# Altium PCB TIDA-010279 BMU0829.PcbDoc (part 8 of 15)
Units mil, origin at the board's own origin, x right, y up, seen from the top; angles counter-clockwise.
Board outline 11269.69 x 4438.98 mil, 4 copper layers (Top Layer, Signal Layer 1, Signal Layer 2, Bottom Layer), stack 61.6 mil thick; 1494 components, 725 nets, 3766 pads, 2728 vias.
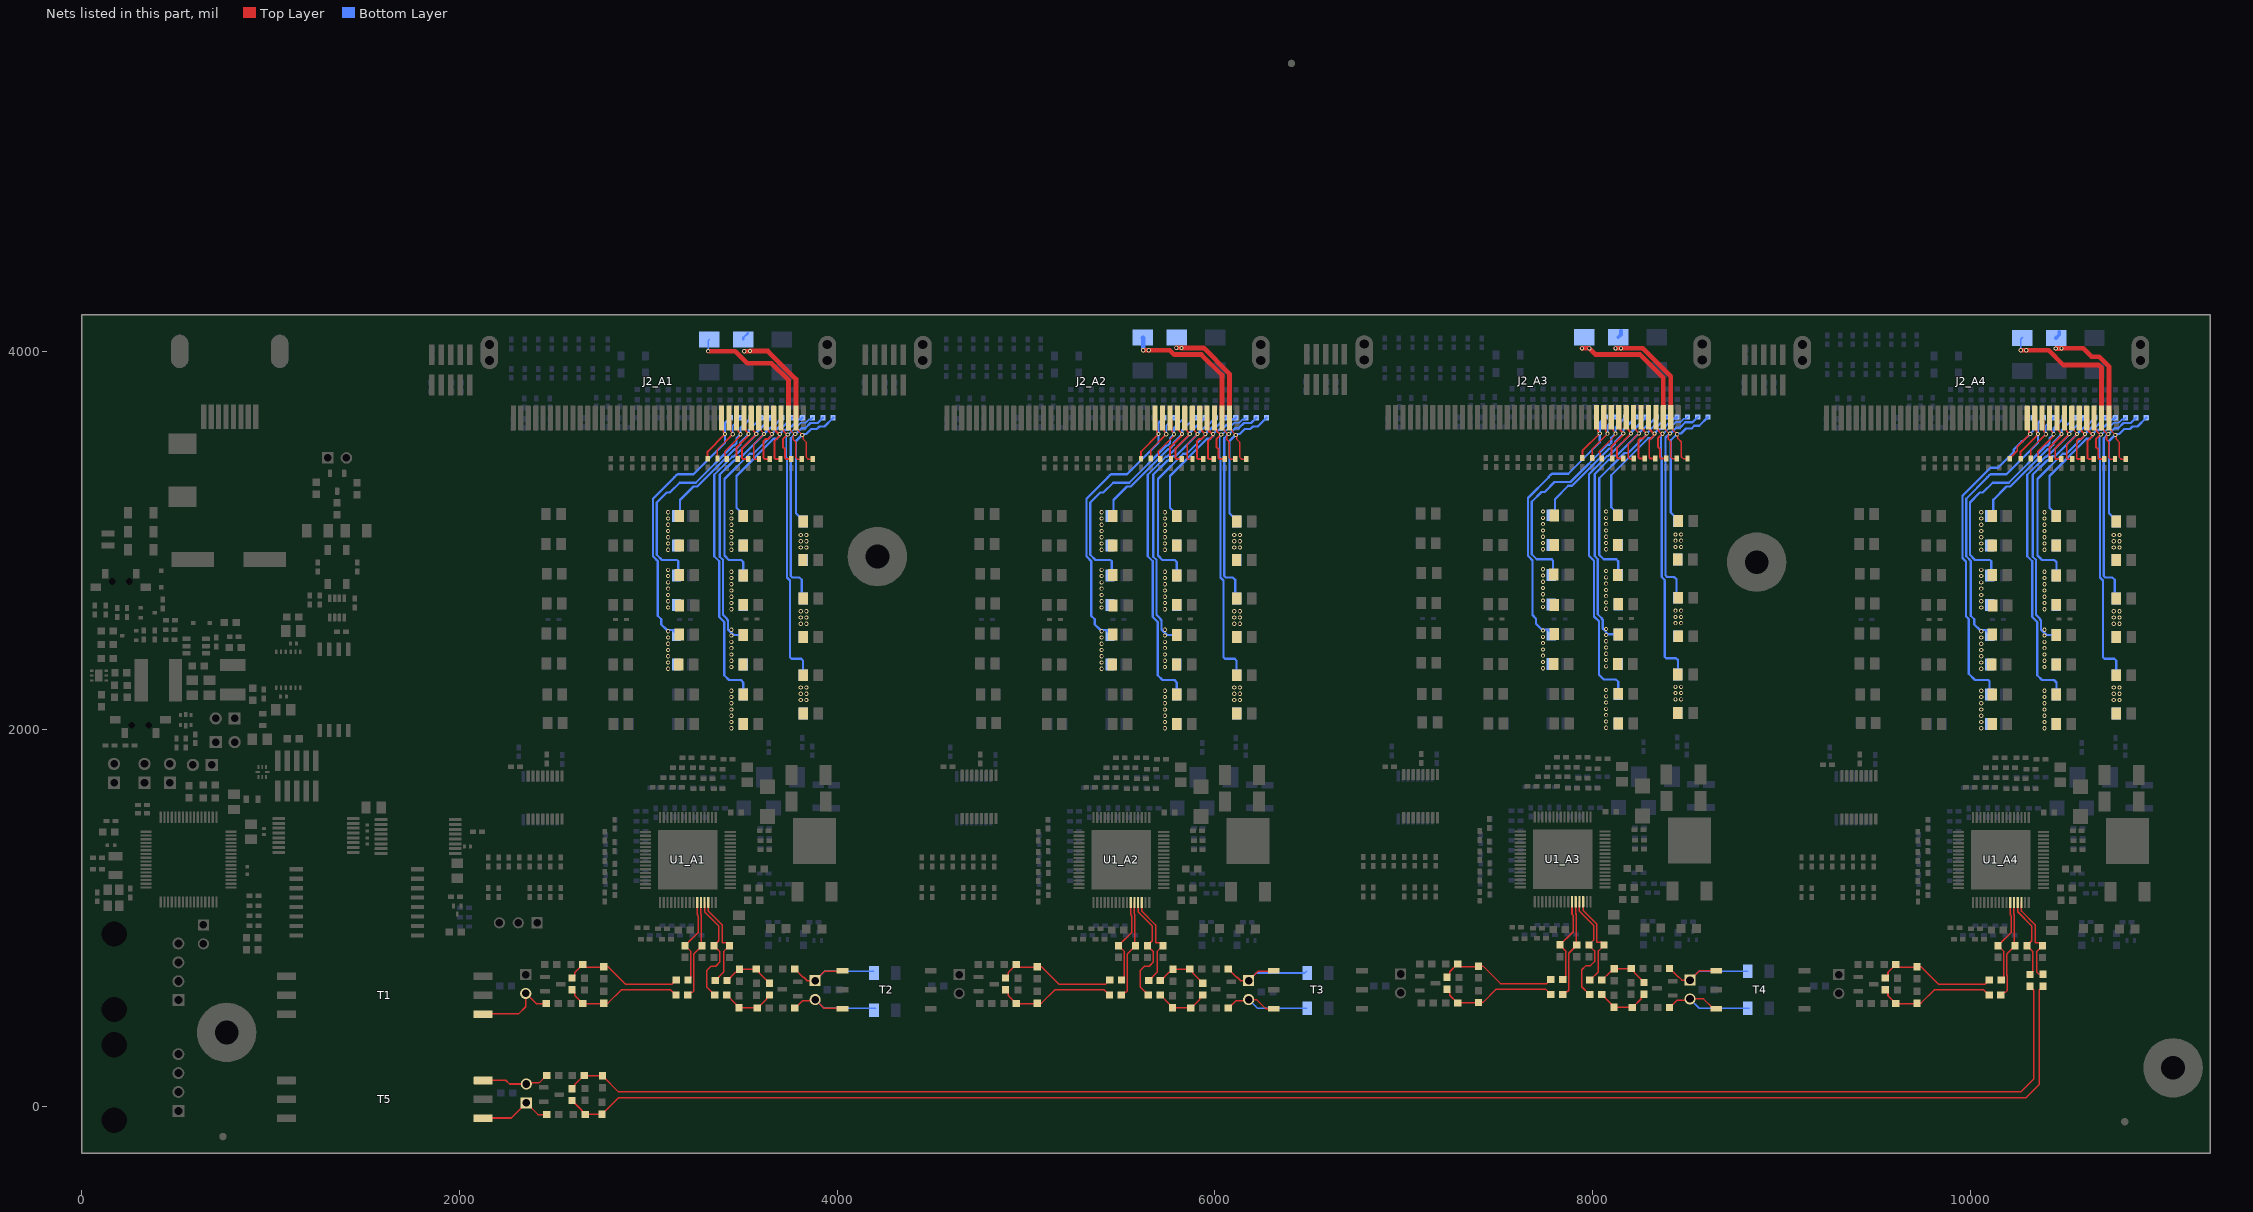
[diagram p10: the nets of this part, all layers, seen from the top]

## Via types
v1: diameter 22.01, hole 12.01, Top Layer to Bottom Layer, tented both sides, 2578 vias
v2: diameter 19.68, hole 7.87, Top Layer to Bottom Layer, tented both sides, 144 vias
v3: diameter 92.52, hole 49.21, Top Layer to Bottom Layer, 4 vias
v4: diameter 19.68, hole 7.87, Top Layer to Bottom Layer, 2 vias

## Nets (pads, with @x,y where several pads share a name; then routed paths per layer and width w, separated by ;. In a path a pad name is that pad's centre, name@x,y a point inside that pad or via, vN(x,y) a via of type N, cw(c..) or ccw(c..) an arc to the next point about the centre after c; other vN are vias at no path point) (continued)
CELL8_A4: C50_A4.1 J2_A4.14 R56_A4.1 R59_A4.1 R63_A4.1 R67_A4.1 R100_A4.1 | length 2015.9
  Top Layer w10: R100_A4.1@10208.36,3431.26 10208.36,3435.19 10247.35,3474.19 10247.35,3494.93 10314.24,3561.81 v1(10316.31,3561.81) 10316.31,3565.06 10309.15,3572.22 10309.15,3638.34 J2_A4.14@10300.37,3647.12
  Bottom Layer w10: 10271.84,3523.52 10278.02,3523.52 v1(10316.31,3561.81) 10316.31,3565.06 10331.52,3580.28 C50_A4.1@10331.52,3648.58
  Bottom Layer w12: R67_A4.1@10100.95,2183.48 10100.95,2252.87 10093.92,2259.9 10024.33,2259.9 9991.15,2293.08 9991.15,2582.34 9976.37,2597.12 9976.37,2886.04 9971.64,2890.76 9971.64,2891.9 9957.23,2906.31 9957.23,3235.23 10106.01,3384.01 10146,3384.01 10228.58,3466.59 10228.58,3480.26 10271.84,3523.52
  other v1: 10056.74,2004.25 10056.74,2037.44 10056.74,2070.62 10056.74,2103.81 10056.74,2136.99 10056.74,2170.17 10056.74,2203.36
CELL9_A1: C47_A1.1 J2_A1.35 R43_A1.1 R46_A1.1 R49_A1.1 R53_A1.1 R90_A1.1 | length 1701.8
  Top Layer w10: R90_A1.1@3313.38,3431.26 3313.38,3469.37 v1(3405.83,3561.81) 3405.83,3565.06 3396.68,3574.21 3396.68,3638.34 J2_A1.35@3387.9,3647.12
  Bottom Layer w12: R46_A1.1@3149.11,2498.57 3149.11,2505.07 3130.11,2524.07 3098.4,2524.07 3068.22,2554.26 3068.22,2581.54 3049.26,2600.5 3049.26,2889.41 3041.06,2897.6 3041.06,2898.74 3025.26,2914.54 3025.26,3219.97 3135.7,3330.41 3135.7,3332.52 3147.34,3344.16 3149.45,3344.16 3154.09,3348.8 3238.9,3348.8 3405.83,3515.73 v1(3405.83,3561.81) 3405.83,3620.11 C47_A1.1@3434.3,3648.58
  other v1: 3104.9,2319.21 3104.9,2352.4 3104.9,2385.58 3104.9,2418.77 3104.9,2451.95 3104.9,2485.14 3104.9,2518.32
CELL9_A2: C47_A2.1 J2_A2.35 R43_A2.1 R46_A2.1 R49_A2.1 R53_A2.1 R90_A2.1 | length 1701.8
  Top Layer w10: R90_A2.1@5608.4,3431.26 5608.4,3469.37 v1(5700.85,3561.81) 5700.85,3565.06 5691.7,3574.21 5691.7,3638.34 J2_A2.35@5682.92,3647.12
  Bottom Layer w12: R46_A2.1@5444.12,2498.57 5444.12,2505.07 5425.12,2524.07 5393.42,2524.07 5363.23,2554.26 5363.23,2581.54 5344.27,2600.5 5344.27,2889.41 5336.08,2897.6 5336.08,2898.74 5320.27,2914.54 5320.27,3219.97 5430.71,3330.41 5430.71,3332.52 5442.35,3344.16 5444.47,3344.16 5449.1,3348.8 5533.92,3348.8 5700.85,3515.73 v1(5700.85,3561.81) 5700.85,3620.11 C47_A2.1@5729.31,3648.58
  other v1: 5399.92,2319.21 5399.92,2352.4 5399.92,2385.58 5399.92,2418.77 5399.92,2451.95 5399.92,2485.14 5399.92,2518.32
CELL9_A3: C47_A3.1 J2_A3.35 R43_A3.1 R46_A3.1 R49_A3.1 R53_A3.1 R90_A3.1 | length 1701.8
  Top Layer w10: R90_A3.1@7945,3434.46 7945,3472.57 v1(8037.44,3565.02) 8037.44,3568.27 8028.29,3577.42 8028.29,3641.55 J2_A3.35@8019.51,3650.33
  Bottom Layer w12: R46_A3.1@7780.72,2501.78 7780.72,2508.28 7761.72,2527.28 7730.02,2527.28 7699.83,2557.47 7699.83,2584.74 7680.87,2603.7 7680.87,2892.62 7672.68,2900.81 7672.68,2901.94 7656.87,2917.75 7656.87,3223.18 7767.31,3333.62 7767.31,3335.73 7778.95,3347.37 7781.06,3347.37 7785.7,3352.01 7870.51,3352.01 8037.44,3518.94 v1(8037.44,3565.02) 8037.44,3623.32 C47_A3.1@8065.91,3651.79
  other v1: 7736.51,2322.42 7736.51,2355.6 7736.51,2388.79 7736.51,2421.97 7736.51,2455.16 7736.51,2488.34 7736.51,2521.53
CELL9_A4: C47_A4.1 J2_A4.35 R43_A4.1 R46_A4.1 R49_A4.1 R53_A4.1 R90_A4.1 | length 1701.8
  Top Layer w10: R90_A4.1@10265.23,3431.26 10265.23,3469.37 v1(10357.67,3561.81) 10357.67,3565.06 10348.52,3574.21 10348.52,3638.34 J2_A4.35@10339.74,3647.12
  Bottom Layer w12: R46_A4.1@10100.95,2498.57 10100.95,2505.07 10081.95,2524.07 10050.25,2524.07 10020.06,2554.26 10020.06,2581.54 10001.1,2600.5 10001.1,2889.41 9992.91,2897.61 9992.91,2898.74 9977.1,2914.54 9977.1,3219.97 10087.54,3330.41 10087.54,3332.52 10099.18,3344.16 10101.29,3344.16 10105.93,3348.8 10190.74,3348.8 10357.67,3515.73 v1(10357.67,3561.81) 10357.67,3620.11 C47_A4.1@10386.14,3648.58
  other v1: 10056.74,2319.21 10056.74,2352.4 10056.74,2385.58 10056.74,2418.77 10056.74,2451.95 10056.74,2485.14 10056.74,2518.32
CELL10_A1: C42_A1.1 J2_A1.36 R28_A1.1 R31_A1.1 R34_A1.1 R39_A1.1 R83_A1.1 | length 1467.6
  Top Layer w8: R83_A1.1@3415.33,3429.13 3408.04,3436.42 3408.04,3456.88 3404.04,3460.88 3404.04,3468.98 3485.87,3550.82 3485.87,3558.37 v1(3488.55,3561.05) 3488.55,3564.84 3476.42,3576.98 3476.42,3637.34 J2_A1.36@3466.64,3647.12
  Bottom Layer w12: R31_A1.1@3149.11,2813.66 3157.85,2822.41 3157.85,2888.35 3150.82,2895.38 3072.53,2895.38 3045.13,2922.78 3045.13,3200.09 3097.29,3252.25 3113.76,3252.25 3165.92,3304.41 3250.73,3304.41 3448.14,3501.83 3455.42,3501.83 3467.07,3513.47 3467.07,3539.56 v1(3488.55,3561.05) 3488.55,3594.16 C42_A1.1@3542.97,3648.58
  other v1: 3104.9,2644.02 3104.9,2677.2 3104.9,2710.38 3104.9,2743.57 3104.9,2776.75 3104.9,2809.94 3104.9,2843.12
CELL10_A2: C42_A2.1 J2_A2.36 R28_A2.1 R31_A2.1 R34_A2.1 R39_A2.1 R83_A2.1 | length 1467.6
  Top Layer w8: R83_A2.1@5710.34,3429.13 5703.05,3436.42 5703.05,3456.88 5699.05,3460.88 5699.05,3468.98 5780.89,3550.82 5780.89,3558.37 v1(5783.57,3561.05) 5783.57,3564.84 5771.44,3576.98 5771.44,3637.34 J2_A2.36@5761.66,3647.12
  Bottom Layer w12: R31_A2.1@5444.12,2813.66 5452.87,2822.41 5452.87,2888.35 5445.84,2895.38 5367.55,2895.38 5340.15,2922.78 5340.15,3200.09 5392.31,3252.25 5408.77,3252.25 5460.93,3304.41 5545.74,3304.41 5743.16,3501.83 5750.44,3501.83 5762.08,3513.47 5762.08,3539.56 v1(5783.57,3561.05) 5783.57,3594.16 C42_A2.1@5837.99,3648.58
  other v1: 5399.92,2644.02 5399.92,2677.2 5399.92,2710.38 5399.92,2743.57 5399.92,2776.75 5399.92,2809.94 5399.92,2843.12
CELL10_A3: C42_A3.1 J2_A3.36 R28_A3.1 R31_A3.1 R34_A3.1 R39_A3.1 R83_A3.1 | length 1467.6
  Top Layer w8: R83_A3.1@8046.94,3432.34 8039.65,3439.63 8039.65,3460.09 8035.65,3464.09 8035.65,3472.19 8117.49,3554.02 8117.49,3561.58 v1(8120.17,3564.26) 8120.17,3568.05 8108.03,3580.18 8108.03,3640.55 J2_A3.36@8098.25,3650.33
  Bottom Layer w12: R31_A3.1@7780.72,2816.87 7789.47,2825.62 7789.47,2891.55 7782.44,2898.58 7704.15,2898.58 7676.74,2925.98 7676.74,3203.3 7728.9,3255.46 7745.37,3255.46 7797.53,3307.62 7882.34,3307.62 8079.76,3505.04 8087.04,3505.04 8098.68,3516.68 8098.68,3542.77 v1(8120.17,3564.26) 8120.17,3597.37 C42_A3.1@8174.58,3651.79
  other v1: 7736.51,2647.22 7736.51,2680.41 7736.51,2713.59 7736.51,2746.78 7736.51,2779.96 7736.51,2813.15 7736.51,2846.33
CELL10_A4: C42_A4.1 J2_A4.36 R28_A4.1 R31_A4.1 R34_A4.1 R39_A4.1 R83_A4.1 | length 1467.6
  Top Layer w8: R83_A4.1@10367.17,3429.13 10359.88,3436.42 10359.88,3456.88 10355.88,3460.88 10355.88,3468.98 10437.72,3550.82 10437.72,3558.37 v1(10440.4,3561.05) 10440.4,3564.84 10428.26,3576.98 10428.26,3637.34 J2_A4.36@10418.48,3647.12
  Bottom Layer w12: R31_A4.1@10100.95,2813.66 10109.7,2822.41 10109.7,2888.35 10102.67,2895.38 10024.37,2895.38 9996.97,2922.78 9996.97,3200.09 10049.13,3252.25 10065.6,3252.25 10117.76,3304.41 10202.57,3304.41 10399.99,3501.83 10407.27,3501.83 10418.91,3513.47 10418.91,3539.56 v1(10440.4,3561.05) 10440.4,3594.16 C42_A4.1@10494.81,3648.58
  other v1: 10056.74,2644.02 10056.74,2677.2 10056.74,2710.38 10056.74,2743.57 10056.74,2776.75 10056.74,2809.94 10056.74,2843.12
CELL11_A1: C39_A1.1 J2_A1.16 R14_A1.1 R17_A1.1 R21_A1.1 R24_A1.1 R75_A1.1 | length 975
  Top Layer w10: R75_A1.1@3472.2,3429.13 3467.38,3433.95 3467.38,3492.52 v1@3533.3,3558.43 ; J2_A1.16@3506.01,3647.12 3514.79,3638.34 3514.79,3580.19 3529.92,3565.06 v1(3529.92,3561.81)
  Bottom Layer w12: R24_A1.1@3149.11,3128.75 3168.11,3147.75 3168.11,3213.54 3239.11,3284.54 3258.96,3284.54 3456.38,3481.96 3463.66,3481.96 3486.94,3505.24 3486.94,3517.94 v1@3530.36,3561.37 ; v1(3529.92,3561.81) 3531.83,3563.73 3531.83,3583.01 C39_A1.1@3597.4,3648.58
  other v1: 3104.9,2949.13 3104.9,2982.32 3104.9,3015.5 3104.9,3048.69 3104.9,3081.87 3104.9,3115.06 3104.9,3148.24
CELL11_A2: C39_A2.1 J2_A2.16 R14_A2.1 R17_A2.1 R21_A2.1 R24_A2.1 R75_A2.1 | length 975
  Top Layer w10: R75_A2.1@5767.21,3429.13 5762.39,3433.95 5762.39,3492.52 v1@5828.31,3558.43 ; J2_A2.16@5801.03,3647.12 5809.81,3638.34 5809.81,3580.19 5824.93,3565.06 v1(5824.93,3561.81)
  Bottom Layer w12: R24_A2.1@5444.12,3128.75 5463.12,3147.75 5463.12,3213.54 5534.13,3284.54 5553.98,3284.54 5751.39,3481.96 5758.67,3481.96 5781.96,3505.24 5781.96,3517.94 v1@5825.38,3561.37 ; v1(5824.93,3561.81) 5826.85,3563.73 5826.85,3583.01 C39_A2.1@5892.42,3648.58
  other v1: 5399.92,2949.13 5399.92,2982.32 5399.92,3015.5 5399.92,3048.69 5399.92,3081.87 5399.92,3115.06 5399.92,3148.24
CELL11_A3: C39_A3.1 J2_A3.16 R14_A3.1 R17_A3.1 R21_A3.1 R24_A3.1 R75_A3.1 | length 975
  Top Layer w10: R75_A3.1@8103.81,3432.34 8098.99,3437.16 8098.99,3495.72 v1@8164.91,3561.64 ; J2_A3.16@8137.62,3650.33 8146.4,3641.55 8146.4,3583.4 8161.53,3568.27 v1(8161.53,3565.02)
  Bottom Layer w12: R24_A3.1@7780.72,3131.96 7799.72,3150.96 7799.72,3216.75 7870.72,3287.75 7890.57,3287.75 8087.99,3485.16 8095.27,3485.16 8118.55,3508.45 8118.55,3521.15 v1@8161.98,3564.57 ; v1(8161.53,3565.02) 8163.44,3566.94 8163.44,3586.21 C39_A3.1@8229.01,3651.79
  other v1: 7736.51,2952.34 7736.51,2985.53 7736.51,3018.71 7736.51,3051.9 7736.51,3085.08 7736.51,3118.27 7736.51,3151.45
CELL11_A4: C39_A4.1 J2_A4.16 R14_A4.1 R17_A4.1 R21_A4.1 R24_A4.1 R75_A4.1 | length 975
  Top Layer w10: R75_A4.1@10424.04,3429.13 10419.22,3433.95 10419.22,3492.52 v1@10485.14,3558.43 ; J2_A4.16@10457.85,3647.12 10466.63,3638.34 10466.63,3580.19 10481.76,3565.06 v1(10481.76,3561.81)
  Bottom Layer w12: R24_A4.1@10100.95,3128.75 10119.95,3147.75 10119.95,3213.54 10190.95,3284.54 10210.8,3284.54 10408.22,3481.96 10415.5,3481.96 10438.78,3505.24 10438.78,3517.94 v1@10482.21,3561.37 ; v1(10481.76,3561.81) 10483.67,3563.73 10483.67,3583.01 C39_A4.1@10549.24,3648.58
  other v1: 10056.74,2949.13 10056.74,2982.32 10056.74,3015.5 10056.74,3048.69 10056.74,3081.87 10056.74,3115.06 10056.74,3148.24
CELL12_A1: C31_A1.1 J2_A1.37 R2_A1.1 R5_A1.1 R8_A1.1 R11_A1.1 R65_A1.1 | length 1984.1
  Top Layer w10: R65_A1.1@3529.06,3429.13 3502.74,3429.13 3496.88,3434.99 3496.88,3487.42 v1@3570.83,3561.37 ; J2_A1.37@3545.38,3647.12 3545.38,3595.94 3558.1,3583.23 3558.1,3577.96 3571.28,3564.78 v1(3571.28,3561.81)
  Bottom Layer w12: R8_A1.1@3503.08,2183.48 3503.08,2246.79 3490.08,2259.79 3426.68,2259.79 3401.5,2284.98 3401.5,2567.11 3375.28,2593.32 3375.28,2888.04 3348.6,2914.72 3348.6,3346.07 3444.8,3442.27 3450.66,3442.27 3470.47,3462.08 3471.89,3462.08 3474.42,3464.62 3476.08,3464.62 v1@3572.28,3560.81 ; v1(3571.28,3561.81) 3573.19,3563.73 3573.19,3569.94 C31_A1.1@3651.83,3648.58
  other v1: 3439.55,2004.25 3439.55,2037.44 3439.55,2070.62 3439.55,2103.81 3439.55,2136.99 3439.55,2170.17 3439.55,2203.36
CELL12_A2: C31_A2.1 J2_A2.37 R2_A2.1 R5_A2.1 R8_A2.1 R11_A2.1 R65_A2.1 | length 1984.1
  Top Layer w10: R65_A2.1@5824.08,3429.13 5797.76,3429.13 5791.9,3434.99 5791.9,3487.42 v1@5865.85,3561.37 ; J2_A2.37@5840.4,3647.12 5840.4,3595.94 5853.11,3583.23 5853.11,3577.96 5866.29,3564.78 v1(5866.29,3561.81)
  Bottom Layer w12: R8_A2.1@5798.1,2183.48 5798.1,2246.79 5785.1,2259.79 5721.7,2259.79 5696.51,2284.98 5696.51,2567.11 5670.3,2593.32 5670.3,2888.04 5643.61,2914.72 5643.61,3346.07 5739.81,3442.27 5745.68,3442.27 5765.49,3462.08 5766.9,3462.08 5769.44,3464.62 5771.1,3464.62 v1@5867.29,3560.81 ; v1(5866.29,3561.81) 5868.21,3563.73 5868.21,3569.94 C31_A2.1@5946.85,3648.58
  other v1: 5734.56,2004.25 5734.56,2037.44 5734.56,2070.62 5734.56,2103.81 5734.56,2136.99 5734.56,2170.17 5734.56,2203.36
CELL12_A3: C31_A3.1 J2_A3.37 R2_A3.1 R5_A3.1 R8_A3.1 R11_A3.1 R65_A3.1 | length 1984.1
  Top Layer w10: R65_A3.1@8160.68,3432.34 8134.35,3432.34 8128.49,3438.2 8128.49,3490.62 v1@8202.45,3564.58 ; J2_A3.37@8176.99,3650.33 8176.99,3599.15 8189.71,3586.43 8189.71,3581.17 8202.89,3567.99 v1(8202.89,3565.02)
  Bottom Layer w12: R8_A3.1@8134.69,2186.69 8134.69,2250 8121.69,2263 8058.3,2263 8033.11,2288.18 8033.11,2570.32 8006.9,2596.53 8006.9,2891.25 7980.21,2917.93 7980.21,3349.28 8076.41,3445.48 8082.28,3445.48 8102.09,3465.29 8103.5,3465.29 8106.03,3467.82 8107.69,3467.82 v1@8203.89,3564.02 ; v1(8202.89,3565.02) 8204.81,3566.94 8204.81,3573.15 C31_A3.1@8283.44,3651.79
  other v1: 8071.16,2007.46 8071.16,2040.64 8071.16,2073.83 8071.16,2107.01 8071.16,2140.2 8071.16,2173.38 8071.16,2206.57
CELL12_A4: C31_A4.1 J2_A4.37 R2_A4.1 R5_A4.1 R8_A4.1 R11_A4.1 R65_A4.1 | length 1984.1
  Top Layer w10: R65_A4.1@10480.91,3429.13 10454.58,3429.13 10448.72,3434.99 10448.72,3487.42 v1@10522.68,3561.37 ; J2_A4.37@10497.22,3647.12 10497.22,3595.94 10509.94,3583.23 10509.94,3577.96 10523.12,3564.78 v1(10523.12,3561.81)
  Bottom Layer w12: R8_A4.1@10454.92,2183.48 10454.92,2246.79 10441.92,2259.79 10378.53,2259.79 10353.34,2284.98 10353.34,2567.11 10327.13,2593.32 10327.13,2888.04 10300.44,2914.72 10300.44,3346.07 10396.64,3442.27 10402.51,3442.27 10422.32,3462.08 10423.73,3462.08 10426.26,3464.62 10427.92,3464.62 v1@10524.12,3560.81 ; v1(10523.12,3561.81) 10525.04,3563.73 10525.04,3569.94 C31_A4.1@10603.67,3648.58
  other v1: 10391.39,2004.25 10391.39,2037.44 10391.39,2070.62 10391.39,2103.81 10391.39,2136.99 10391.39,2170.17 10391.39,2203.36
CELL13_A1: C27_A1.1 J2_A1.17 R61_A1.1 R71_A1.1 R74_A1.1 R78_A1.1 R82_A1.1 | length 1661
  Top Layer w8: J2_A1.17@3584.75,3647.12 3584.75,3595.94 3598.47,3582.23 3598.47,3578.37 3612.64,3564.2 v1(3612.64,3561.81) ; R61_A1.1@3585.93,3429.13 3562.12,3429.13 3557.43,3433.82 3557.43,3506.6 v1@3612.2,3561.37
  Bottom Layer w12: R82_A1.1@3503.08,2498.57 3450.45,2498.57 3421.37,2527.65 3421.37,2575.34 3416.41,2580.3 3416.41,2584.15 3395.16,2605.4 3395.16,2896.27 3378.45,2912.97 3378.45,3347.82 3453.03,3422.4 3458.89,3422.4 3478.71,3442.21 3480.12,3442.21 3482.65,3444.74 3495.58,3444.74 v1@3612.2,3561.37 ; v1(3612.64,3561.81) 3653.09,3602.26 3659.95,3602.26 C27_A1.1@3706.26,3648.58
  other v1: 3439.55,2329.05 3439.55,2362.24 3439.55,2395.42 3439.55,2428.61 3439.55,2461.79 3439.55,2494.98 3439.55,2526.33
CELL13_A2: C27_A2.1 J2_A2.17 R61_A2.1 R71_A2.1 R74_A2.1 R78_A2.1 R82_A2.1 | length 1661
  Top Layer w8: J2_A2.17@5879.77,3647.12 5879.77,3595.94 5893.48,3582.23 5893.48,3578.37 5907.66,3564.2 v1(5907.66,3561.81) ; R61_A2.1@5880.95,3429.13 5857.14,3429.13 5852.45,3433.82 5852.45,3506.6 v1@5907.22,3561.37
  Bottom Layer w12: R82_A2.1@5798.1,2498.57 5745.46,2498.57 5716.39,2527.65 5716.39,2575.34 5711.42,2580.3 5711.42,2584.15 5690.17,2605.4 5690.17,2896.27 5673.47,2912.97 5673.47,3347.82 5748.04,3422.4 5753.91,3422.4 5773.72,3442.21 5775.14,3442.21 5777.67,3444.74 5790.59,3444.74 v1@5907.22,3561.37 ; v1(5907.66,3561.81) 5948.11,3602.26 5954.96,3602.26 C27_A2.1@6001.28,3648.58
  other v1: 5734.56,2329.05 5734.56,2362.24 5734.56,2395.42 5734.56,2428.61 5734.56,2461.79 5734.56,2494.98 5734.56,2526.33
CELL13_A3: C27_A3.1 J2_A3.17 R61_A3.1 R71_A3.1 R74_A3.1 R78_A3.1 R82_A3.1 | length 1661
  Top Layer w8: J2_A3.17@8216.36,3650.33 8216.36,3599.15 8230.08,3585.43 8230.08,3581.58 8244.25,3567.41 v1(8244.25,3565.02) ; R61_A3.1@8217.54,3432.34 8193.73,3432.34 8189.05,3437.03 8189.05,3509.81 v1@8243.82,3564.58
  Bottom Layer w12: R82_A3.1@8134.69,2501.78 8082.06,2501.78 8052.98,2530.86 8052.98,2578.55 8048.02,2583.51 8048.02,2587.36 8026.77,2608.61 8026.77,2899.48 8010.07,2916.18 8010.07,3351.03 8084.64,3425.61 8090.51,3425.61 8110.32,3445.42 8111.73,3445.42 8114.27,3447.95 8127.19,3447.95 v1@8243.82,3564.58 ; v1(8244.25,3565.02) 8284.7,3605.47 8291.56,3605.47 C27_A3.1@8337.88,3651.79
  other v1: 8071.16,2332.26 8071.16,2365.45 8071.16,2398.63 8071.16,2431.82 8071.16,2465 8071.16,2498.19 8071.16,2529.54
CELL13_A4: C27_A4.1 J2_A4.17 R61_A4.1 R71_A4.1 R74_A4.1 R78_A4.1 R82_A4.1 | length 1661
  Top Layer w8: J2_A4.17@10536.59,3647.12 10536.59,3595.94 10550.31,3582.23 10550.31,3578.37 10564.48,3564.2 v1(10564.48,3561.81) ; R61_A4.1@10537.77,3429.13 10513.96,3429.13 10509.28,3433.82 10509.28,3506.6 v1@10564.05,3561.37
  Bottom Layer w12: R82_A4.1@10454.92,2498.57 10402.29,2498.57 10373.21,2527.65 10373.21,2575.34 10368.25,2580.3 10368.25,2584.15 10347,2605.4 10347,2896.27 10330.3,2912.97 10330.3,3347.82 10404.87,3422.4 10410.74,3422.4 10430.55,3442.21 10431.96,3442.21 10434.5,3444.74 10447.42,3444.74 v1@10564.05,3561.37 ; v1(10564.48,3561.81) 10604.93,3602.26 10611.79,3602.26 C27_A4.1@10658.11,3648.58
  other v1: 10391.39,2329.05 10391.39,2362.24 10391.39,2395.42 10391.39,2428.61 10391.39,2461.79 10391.39,2494.98 10391.39,2526.33
CELL14_A1: C23_A1.1 J2_A1.38 R51_A1.1 R57_A1.1 R60_A1.1 R64_A1.1 R68_A1.1 | length 1367.8
  Top Layer w10: J2_A1.38@3624.12,3647.12 3624.12,3595.94 3636.84,3583.23 3636.84,3577.96 3652.99,3561.81 v1(3654,3561.81) ; R51_A1.1@3642.8,3429.13 3616.47,3429.13 3610.62,3434.99 3610.62,3526.01 3620.78,3536.17 3634,3536.17 v1@3656.82,3558.99
  Bottom Layer w12: R68_A1.1@3503.08,2813.66 3503.08,2884.71 3492.3,2895.5 3426.38,2895.5 3403.23,2918.65 3403.23,3324.29 3537.11,3458.17 3556,3458.17 v1@3656.82,3558.99 ; v1(3654,3561.81) 3694.45,3602.26 3714.38,3602.26 C23_A1.1@3760.69,3648.58
  other v1: 3439.55,2634.17 3439.55,2667.36 3439.55,2700.54 3439.55,2733.73 3439.55,2766.91 3439.55,2800.1 3439.55,2833.28
CELL14_A2: C23_A2.1 J2_A2.38 R51_A2.1 R57_A2.1 R60_A2.1 R64_A2.1 R68_A2.1 | length 1367.8
  Top Layer w10: J2_A2.38@5919.14,3647.12 5919.14,3595.94 5931.85,3583.23 5931.85,3577.96 5948,3561.81 v1(5949.02,3561.81) ; R51_A2.1@5937.82,3429.13 5911.49,3429.13 5905.63,3434.99 5905.63,3526.01 5915.79,3536.17 5929.02,3536.17 v1@5951.84,3558.99
  Bottom Layer w12: R68_A2.1@5798.1,2813.66 5798.1,2884.71 5787.31,2895.5 5721.4,2895.5 5698.25,2918.65 5698.25,3324.29 5832.13,3458.17 5851.01,3458.17 v1@5951.84,3558.99 ; v1(5949.02,3561.81) 5989.47,3602.26 6009.39,3602.26 C23_A2.1@6055.71,3648.58
  other v1: 5734.56,2634.17 5734.56,2667.36 5734.56,2700.54 5734.56,2733.73 5734.56,2766.91 5734.56,2800.1 5734.56,2833.28
CELL14_A3: C23_A3.1 J2_A3.38 R51_A3.1 R57_A3.1 R60_A3.1 R64_A3.1 R68_A3.1 | length 1367.8
  Top Layer w10: J2_A3.38@8255.73,3650.33 8255.73,3599.15 8268.45,3586.43 8268.45,3581.17 8284.6,3565.02 v1(8285.62,3565.02) ; R51_A3.1@8274.41,3432.34 8248.09,3432.34 8242.23,3438.2 8242.23,3529.22 8252.39,3539.38 8265.62,3539.38 v1@8288.44,3562.2
  Bottom Layer w12: R68_A3.1@8134.69,2816.87 8134.69,2887.92 8123.91,2898.71 8057.99,2898.71 8034.84,2921.86 8034.84,3327.5 8168.72,3461.38 8187.61,3461.38 v1@8288.44,3562.2 ; v1(8285.62,3565.02) 8326.06,3605.47 8345.99,3605.47 C23_A3.1@8392.31,3651.79
  other v1: 8071.16,2637.38 8071.16,2670.57 8071.16,2703.75 8071.16,2736.93 8071.16,2770.12 8071.16,2803.3 8071.16,2836.49
CELL14_A4: C23_A4.1 J2_A4.38 R51_A4.1 R57_A4.1 R60_A4.1 R64_A4.1 R68_A4.1 | length 1367.8
  Top Layer w10: J2_A4.38@10575.96,3647.12 10575.96,3595.94 10588.68,3583.23 10588.68,3577.96 10604.83,3561.81 v1(10605.85,3561.81) ; R51_A4.1@10594.64,3429.13 10568.32,3429.13 10562.46,3434.99 10562.46,3526.01 10572.62,3536.17 10585.85,3536.17 v1@10608.67,3558.99
  Bottom Layer w12: R68_A4.1@10454.92,2813.66 10454.92,2884.72 10444.14,2895.5 10378.22,2895.5 10355.07,2918.65 10355.07,3324.29 10488.95,3458.17 10507.84,3458.17 v1@10608.67,3558.99 ; v1(10605.85,3561.81) 10646.29,3602.26 10666.22,3602.26 C23_A4.1@10712.54,3648.58
  other v1: 10391.39,2634.17 10391.39,2667.36 10391.39,2700.54 10391.39,2733.73 10391.39,2766.91 10391.39,2800.1 10391.39,2833.28
CELL15_A1: C19_A1.1 J2_A1.18 R41_A1.1 R44_A1.1 R47_A1.1 R50_A1.1 R54_A1.1 | length 977
  Top Layer w10: R41_A1.1@3699.67,3429.13 3673.34,3429.13 3667.48,3434.99 3667.48,3524.82 v1@3699.92,3557.26
  Top Layer w12: J2_A1.18@3663.49,3647.12 3671.27,3639.34 3671.27,3581.48 3689.03,3563.73 3693.45,3563.73 v1(3695.36,3561.81)
  Bottom Layer w12: R50_A1.1@3503.08,3128.75 3503.08,3135.25 3466.7,3171.64 3466.7,3340.6 3662.74,3536.65 3679.31,3536.65 v1@3699.92,3557.26 ; v1(3695.36,3561.81) 3715.94,3582.39 3722.61,3582.39 3725.22,3585 3740.82,3585 3768.71,3612.9 3771.07,3612.9 3798.96,3640.8 3807.34,3640.8 C19_A1.1@3815.12,3648.58
  other v1: 3439.55,2949.13 3439.55,2982.32 3439.55,3015.5 3439.55,3048.69 3439.55,3081.87 3439.55,3115.06 3439.55,3148.24
CELL15_A2: C19_A2.1 J2_A2.18 R41_A2.1 R44_A2.1 R47_A2.1 R50_A2.1 R54_A2.1 | length 977
  Top Layer w10: R41_A2.1@5994.68,3429.13 5968.36,3429.13 5962.5,3434.99 5962.5,3524.82 v1@5994.94,3557.26
  Top Layer w12: J2_A2.18@5958.51,3647.12 5966.29,3639.34 5966.29,3581.48 5984.04,3563.73 5988.47,3563.73 v1(5990.38,3561.81)
  Bottom Layer w12: R50_A2.1@5798.1,3128.75 5798.1,3135.25 5761.71,3171.64 5761.71,3340.6 5957.76,3536.65 5974.33,3536.65 v1@5994.94,3557.26 ; v1(5990.38,3561.81) 6010.96,3582.39 6017.63,3582.39 6020.24,3585 6035.83,3585 6063.73,3612.9 6066.08,3612.9 6093.98,3640.8 6102.36,3640.8 C19_A2.1@6110.14,3648.58
  other v1: 5734.56,2949.13 5734.56,2982.32 5734.56,3015.5 5734.56,3048.69 5734.56,3081.87 5734.56,3115.06 5734.56,3148.24
CELL15_A3: C19_A3.1 J2_A3.18 R41_A3.1 R44_A3.1 R47_A3.1 R50_A3.1 R54_A3.1 | length 977
  Top Layer w10: R41_A3.1@8331.28,3432.34 8304.96,3432.34 8299.1,3438.2 8299.1,3528.03 v1@8331.53,3560.47
  Top Layer w12: J2_A3.18@8295.1,3650.33 8302.88,3642.55 8302.88,3584.69 8320.64,3566.94 8325.06,3566.94 v1(8326.98,3565.02)
  Bottom Layer w12: R50_A3.1@8134.69,3131.96 8134.69,3138.46 8098.31,3174.85 8098.31,3343.81 8294.36,3539.86 8310.92,3539.86 v1@8331.53,3560.47 ; v1(8326.98,3565.02) 8347.55,3585.6 8354.22,3585.6 8356.84,3588.21 8372.43,3588.21 8400.33,3616.11 8402.68,3616.11 8430.58,3644.01 8438.96,3644.01 C19_A3.1@8446.74,3651.79
  other v1: 8071.16,2952.34 8071.16,2985.53 8071.16,3018.71 8071.16,3051.9 8071.16,3085.08 8071.16,3118.27 8071.16,3151.45
CELL15_A4: C19_A4.1 J2_A4.18 R41_A4.1 R44_A4.1 R47_A4.1 R50_A4.1 R54_A4.1 | length 977
  Top Layer w10: R41_A4.1@10651.51,3429.13 10625.19,3429.13 10619.33,3434.99 10619.33,3524.82 v1@10651.76,3557.26
  Top Layer w12: J2_A4.18@10615.33,3647.12 10623.11,3639.34 10623.11,3581.48 10640.87,3563.73 10645.29,3563.73 v1(10647.21,3561.81)
  Bottom Layer w12: R50_A4.1@10454.92,3128.75 10454.92,3135.25 10418.54,3171.64 10418.54,3340.6 10614.59,3536.65 10631.15,3536.65 v1@10651.76,3557.26 ; v1(10647.21,3561.81) 10667.78,3582.39 10674.45,3582.39 10677.07,3585 10692.66,3585 10720.56,3612.9 10722.91,3612.9 10750.81,3640.8 10759.19,3640.8 C19_A4.1@10766.97,3648.58
  other v1: 10391.39,2949.13 10391.39,2982.32 10391.39,3015.5 10391.39,3048.69 10391.39,3081.87 10391.39,3115.06 10391.39,3148.24
CELL16_A1: C11_A1.1 J2_A1.39 R29_A1.1 R32_A1.1 R35_A1.1 R37_A1.1 R40_A1.1 | length 1781.9
  Top Layer w10: J2_A1.39@3702.86,3647.12 3702.86,3595.94 3715.58,3583.23 3715.58,3577.96 v1@3729.43,3564.11 ; v1@3737.39,3560.97 3713.23,3536.8 3713.23,3491.46 3724.35,3480.33 3724.35,3434.99 3730.21,3429.13 R37_A1.1@3756.54,3429.13
  Bottom Layer w10: 3730.31,3435.04 3730.31,3548.77 3738.42,3556.87 v1(3738.42,3560.12) v1@3740.71,3562.42 ; v1@3740.16,3562.99 3740.73,3562.42 3743.96,3562.42 3744.54,3562.99 3745.5,3562.99 3776.53,3594.03 3778.88,3594.03 3806.78,3621.92 3833.11,3621.92 3850.98,3639.8 3860.77,3639.8 C11_A1.1@3869.55,3648.58
  Bottom Layer w12: 3733.91,3435.04 3733.91,2802.5 3750.19,2786.23 3750.19,2379.81 3757.95,2372.05 3809.61,2372.05 3819.45,2362.2 R32_A1.1@3819.45,2285.08
  other v1: 3807.09,2154.1 3836.62,2154.1 3807.09,2187.29 3836.62,2187.29 3807.09,2220.47 3836.62,2220.47
CELL16_A2: C11_A2.1 J2_A2.39 R29_A2.1 R32_A2.1 R35_A2.1 R37_A2.1 R40_A2.1 | length 1781.9
  Top Layer w10: J2_A2.39@5997.88,3647.12 5997.88,3595.94 6010.59,3583.23 6010.59,3577.96 v1@6024.44,3564.11 ; v1@6032.41,3560.97 6008.25,3536.8 6008.25,3491.46 6019.37,3480.33 6019.37,3434.99 6025.23,3429.13 R37_A2.1@6051.55,3429.13
  Bottom Layer w10: 6025.33,3435.04 6025.33,3548.77 6033.43,3556.87 v1(6033.43,3560.12) v1@6035.73,3562.42 ; v1@6035.17,3562.99 v1@6035.74,3562.42 ; C11_A2.1@6164.57,3648.58 6155.79,3639.8 6146,3639.8 6128.12,3621.92 6101.8,3621.92 6073.9,3594.03 6071.55,3594.03 6040.52,3562.99 6039.55,3562.99 6038.98,3562.42 v1@6035.74,3562.42
  Bottom Layer w12: 6028.93,3435.04 6028.93,2802.5 6045.2,2786.23 6045.2,2379.81 6052.97,2372.05 6104.63,2372.05 6114.47,2362.2 R32_A2.1@6114.47,2285.08
  other v1: 6102.1,2154.1 6131.63,2154.1 6102.1,2187.29 6131.63,2187.29 6102.1,2220.47 6131.63,2220.47
CELL16_A3: C11_A3.1 J2_A3.39 R29_A3.1 R32_A3.1 R35_A3.1 R37_A3.1 R40_A3.1 | length 1781.9
  Top Layer w10: J2_A3.39@8334.48,3650.33 8334.48,3599.15 8347.19,3586.43 8347.19,3581.17 v1@8361.04,3567.32 ; v1@8369.01,3564.17 8344.84,3540.01 8344.84,3494.67 8355.97,3483.54 8355.97,3438.2 8361.82,3432.34 R37_A3.1@8388.15,3432.34
  Bottom Layer w10: 8361.93,3438.25 8361.93,3551.98 8370.03,3560.08 v1(8370.03,3563.33) v1@8372.33,3565.63 ; v1@8371.77,3566.2 v1@8372.34,3565.63 ; C11_A3.1@8501.17,3651.79 8492.39,3643.01 8482.59,3643.01 8464.72,3625.13 8438.39,3625.13 8410.5,3597.23 8408.15,3597.23 8377.11,3566.2 8376.15,3566.2 8375.58,3565.63 v1@8372.34,3565.63
  Bottom Layer w12: 8365.52,3438.25 8365.52,2805.71 8381.8,2789.43 8381.8,2383.02 8389.57,2375.26 8441.22,2375.26 8451.06,2365.41 R32_A3.1@8451.06,2288.29
  other v1: 8438.7,2157.31 8468.23,2157.31 8438.7,2190.5 8468.23,2190.5 8438.7,2223.68 8468.23,2223.68
CELL16_A4: C11_A4.1 J2_A4.39 R29_A4.1 R32_A4.1 R35_A4.1 R37_A4.1 R40_A4.1 | length 1781.9
  Top Layer w10: J2_A4.39@10654.7,3647.12 10654.7,3595.94 10667.42,3583.23 10667.42,3577.96 v1@10681.27,3564.11 ; v1@10689.24,3560.97 10665.07,3536.8 10665.07,3491.46 10676.19,3480.33 10676.19,3434.99 10682.05,3429.13 R37_A4.1@10708.38,3429.13
  Bottom Layer w10: 10682.16,3435.04 10682.16,3548.77 10690.26,3556.87 v1(10690.26,3560.12) v1@10692.56,3562.42 ; v1@10692,3562.99 v1@10692.57,3562.42 ; C11_A4.1@10821.4,3648.58 10812.62,3639.8 10802.82,3639.8 10784.95,3621.92 10758.62,3621.92 10730.73,3594.03 10728.37,3594.03 10697.34,3562.99 10696.38,3562.99 10695.81,3562.42 v1@10692.57,3562.42
  Bottom Layer w12: 10685.75,3435.04 10685.75,2802.5 10702.03,2786.23 10702.03,2379.81 10709.8,2372.05 10761.45,2372.05 10771.29,2362.2 R32_A4.1@10771.29,2285.08
  other v1: 10758.93,2154.1 10788.46,2154.1 10758.93,2187.29 10788.46,2187.29 10758.93,2220.47 10788.46,2220.47
CELL17_A1: C8_A1.1 D7_A1.1 J2_A1.19 R15_A1.1 R18_A1.1 R22_A1.1 R25_A1.1 R26_A1.1 | length 2138.5
  Top Layer w8: J2_A1.19@3742.23,3647.12 3742.23,3595.94 3755.95,3582.23 3755.95,3578.37 3769.83,3564.49 3775.41,3564.49 v1(3778.09,3561.81) ; v1@3776.76,3559.49 3768.33,3551.06 3768.33,3532.02 3780.22,3520.13 3780.22,3438.51 3789.59,3429.13 R26_A1.1@3813.4,3429.13
  Top Layer w25: v1(3316.71,4000.94) 3460.29,4000.94 3524.23,3937.01 3651.57,3937.01 3742.23,3846.35 J2_A1.19@3742.23,3647.12
  Bottom Layer w8: v1@3316.93,3996.06 3316.71,3996.28 v1(3316.71,4000.94) 3316.71,4056.99 D7_A1.1@3323.11,4063.39
  Bottom Layer w12: v1@3776.69,3563.21 3753.78,3540.31 3753.78,2810.74 3761.91,2802.61 3799.21,2802.61 3811.67,2790.16 3811.67,2699.73 R15_A1.1@3819.45,2691.94 ; v1@3779.96,3561.81 3810.47,3592.33 3830.2,3592.33 3858.8,3620.92 3896.33,3620.92 C8_A1.1@3923.98,3648.58
  other v1: 3807.09,2557.65 3836.62,2557.65 3807.09,2590.83 3836.62,2590.83 3807.09,2624.02 3836.62,2624.02
CELL17_A2: C8_A2.1 D7_A2.1 J2_A2.19 R15_A2.1 R18_A2.1 R22_A2.1 R25_A2.1 R26_A2.1 | length 2147.8
  Top Layer w8: J2_A2.19@6037.25,3647.12 6037.25,3595.94 6050.96,3582.23 6050.96,3578.37 6064.85,3564.49 6070.42,3564.49 v1(6073.1,3561.81) ; v1@6071.78,3559.49 6063.34,3551.06 6063.34,3532.02 6075.24,3520.13 6075.24,3438.51 6084.61,3429.13 R26_A2.1@6108.42,3429.13
  Top Layer w25: v1(5620.08,4005.91) 5761.74,4005.91 5784.77,3982.87 5928.54,3982.87 6037.25,3874.17 J2_A2.19@6037.25,3647.12
  Bottom Layer w12: v1@6071.71,3563.21 6048.8,3540.31 6048.8,2810.74 6056.93,2802.61 6094.23,2802.61 6106.68,2790.16 6106.68,2699.73 R15_A2.1@6114.47,2691.94 ; v1(6073.1,3561.81) 6074.98,3561.81 6105.49,3592.33 6125.22,3592.33 6153.81,3620.92 6191.35,3620.92 C8_A2.1@6219,3648.58
  Bottom Layer w25: D7_A2.1@5617.8,4072.41 5620.08,4070.14 v1(5620.08,4005.91)
  other v1: 6102.1,2557.65 6131.63,2557.65 6102.1,2590.83 6131.63,2590.83 6102.1,2624.02 6131.63,2624.02 5649.61,4005.91
CELL17_A3: C8_A3.1 D7_A3.1 J2_A3.19 R15_A3.1 R18_A3.1 R22_A3.1 R25_A3.1 R26_A3.1 | length 2086.9
  Top Layer w8: J2_A3.19@8373.85,3650.33 8373.85,3599.15 8387.56,3585.43 8387.56,3581.58 8401.44,3567.7 8407.02,3567.7 v1(8409.7,3565.02) ; v1@8408.37,3562.7 8399.94,3554.27 8399.94,3535.23 8411.83,3523.33 8411.83,3441.71 8421.2,3432.34 R26_A3.1@8445.02,3432.34
  Top Layer w25: v1(7942.91,4015.75) v1(7982.28,4015.75) 8015.16,3982.87 8251.38,3982.87 8373.85,3860.41 J2_A3.19@8373.85,3650.33
  Bottom Layer w12: v1@8408.3,3566.42 8385.4,3543.52 8385.4,2813.94 8393.52,2805.82 8430.83,2805.82 8443.28,2793.36 8443.28,2702.94 R15_A3.1@8451.06,2695.15 ; v1(8409.7,3565.02) 8411.57,3565.02 8442.09,3595.53 8461.81,3595.53 8490.41,3624.13 8527.94,3624.13 C8_A3.1@8555.6,3651.79
  other v1: 8438.7,2560.86 8468.23,2560.86 8438.7,2594.04 8468.23,2594.04 8438.7,2627.23 8468.23,2627.23
CELL17_A4: C8_A4.1 D7_A4.1 J2_A4.19 R15_A4.1 R18_A4.1 R22_A4.1 R25_A4.1 R26_A4.1 | length 2186.9
  Top Layer w8: J2_A4.19@10694.08,3647.12 10694.08,3595.94 10707.79,3582.23 10707.79,3578.37 10721.67,3564.49 10727.25,3564.49 v1(10729.93,3561.81) ; v1@10728.6,3559.49 10720.17,3551.06 10720.17,3532.02 10732.06,3520.13 10732.06,3438.51 10741.43,3429.13 R26_A4.1@10765.25,3429.13
  Top Layer w25: v1(10265.75,4005.91) v1(10295.28,4005.91) 10413.75,4005.91 10492.49,3927.17 10679.43,3927.17 10694.08,3912.52 J2_A4.19@10694.08,3647.12
  Bottom Layer w7: v1(10265.75,4005.91) 10265.75,4064.96 D7_A4.1@10275.59,4074.8
  Bottom Layer w12: v1@10728.53,3563.21 10705.63,3540.31 10705.63,2810.74 10713.75,2802.61 10751.06,2802.61 10763.51,2790.16 10763.51,2699.73 R15_A4.1@10771.29,2691.94 ; v1(10729.93,3561.81) 10731.8,3561.81 10762.32,3592.33 10782.04,3592.33 10810.64,3620.92 10848.17,3620.92 C8_A4.1@10875.83,3648.58
  other v1: 10758.93,2557.65 10788.46,2557.65 10758.93,2590.83 10788.46,2590.83 10758.93,2624.02 10788.46,2624.02
CELL18_A1: C5_A1.1 D8_A1.1 J2_A1.40 R3_A1.1 R6_A1.1 R9_A1.1 R12_A1.1 R19_A1.1 | length 1537.4
  Top Layer w8: J2_A1.40@3781.6,3647.12 3781.6,3595.94 3795.32,3582.23 3795.32,3577.59 v1(3815.27,3557.64) 3815.27,3553.84 3819.45,3549.67 3819.45,3535.24 3837.09,3517.61 3837.09,3438.51 3846.46,3429.13 R19_A1.1@3870.27,3429.13
  Top Layer w25: v1(3507.45,4000.27) v1@3538.03,4000.27 ; v1(3538.03,4001.58) 3633.5,4001.58 3781.6,3853.47 J2_A1.40@3781.6,3647.12
  Bottom Layer w12: D8_A1.1@3503.08,4063.38 3503.08,4072.23 D8_A1.1@3527.03,4096.18 ; v1@3815.27,3554.93 v1(3815.27,3557.64) 3813.8,3557.64 3781.63,3525.46 3781.63,3143.13 3819.45,3105.31 R12_A1.1@3819.45,3098.81 ; v1@3822.16,3561.81 3835.74,3561.81 3862.62,3588.69 3892.2,3588.69 3905.78,3602.26 3932.1,3602.26 C5_A1.1@3978.41,3648.58
  other v1: 3807.09,2961.19 3836.62,2961.19 3807.09,2994.38 3836.62,2994.38 3807.09,3027.56 3836.62,3027.56
CELL18_A2: C5_A2.1 D8_A2.1 J2_A2.40 R3_A2.1 R6_A2.1 R9_A2.1 R12_A2.1 R19_A2.1 | length 1525.1
  Top Layer w8: J2_A2.40@6076.62,3647.12 6076.62,3595.94 6090.33,3582.23 6090.33,3577.59 v1(6110.29,3557.64) 6110.29,3553.84 6114.47,3549.67 6114.47,3535.24 6132.1,3517.61 6132.1,3438.51 6141.48,3429.13 R19_A2.1@6165.29,3429.13
  Top Layer w25: v1(5795.48,4018.65) 5821.87,4018.65 v1(5822.57,4017.94) 5939.97,4017.94 6076.62,3881.29 J2_A2.40@6076.62,3647.12
  Bottom Layer w12: v1@6110.29,3554.93 v1(6110.29,3557.64) 6108.82,3557.64 6076.64,3525.46 6076.64,3143.13 6114.47,3105.31 R12_A2.1@6114.47,3098.81 ; v1@6117.18,3561.81 6130.76,3561.81 6157.64,3588.69 6187.22,3588.69 6200.79,3602.26 6227.12,3602.26 C5_A2.1@6273.43,3648.58
  other v1: 6102.1,2961.19 6131.63,2961.19 6102.1,2994.38 6131.63,2994.38 6102.1,3027.56 6131.63,3027.56
CELL18_A3: C5_A3.1 D8_A3.1 J2_A3.40 R3_A3.1 R6_A3.1 R9_A3.1 R12_A3.1 R19_A3.1 | length 1563.2
  Top Layer w8: J2_A3.40@8413.22,3650.33 8413.22,3599.15 8426.93,3585.43 8426.93,3580.8 v1(8446.89,3560.84) 8446.89,3557.05 8451.06,3552.87 8451.06,3538.45 8468.7,3520.82 8468.7,3441.71 8478.07,3432.34 R19_A3.1@8501.88,3432.34
  Top Layer w25: v1(8120.08,4015.75) 8264.99,4015.75 8413.22,3867.53 J2_A3.40@8413.22,3650.33
  Bottom Layer w12: v1@8446.89,3558.14 v1(8446.89,3560.84) 8445.42,3560.84 8413.24,3528.67 8413.24,3146.34 8451.06,3108.51 R12_A3.1@8451.06,3102.01 ; v1@8453.77,3565.02 8467.36,3565.02 8494.23,3591.9 8523.81,3591.9 8537.39,3605.47 8563.71,3605.47 C5_A3.1@8610.03,3651.79
  Bottom Layer w20: D8_A3.1@8134.69,4074.6 8149.47,4089.38 D8_A3.1@8149.47,4107.1
  other v1: 8438.7,2964.4 8468.23,2964.4 8438.7,2997.58 8468.23,2997.58 8438.7,3030.77 8468.23,3030.77 8149.61,4015.75
CELL18_A4: C5_A4.1 D8_A4.1 J2_A4.40 R3_A4.1 R6_A4.1 R9_A4.1 R12_A4.1 R19_A4.1 | length 1586.3
  Top Layer w8: J2_A4.40@10733.45,3647.12 10733.45,3595.94 10747.16,3582.23 10747.16,3577.59 v1(10767.12,3557.64) 10767.12,3553.84 10771.29,3549.67 10771.29,3535.24 10788.93,3517.61 10788.93,3438.51 10798.3,3429.13 R19_A4.1@10822.11,3429.13
  Top Layer w25: v1(10451.7,4014.44) v1@10482.28,4014.44 ; v1(10482.28,4015.75) 10596.04,4015.75 10640.85,3970.94 10682.14,3970.94 10733.45,3919.64 J2_A4.40@10733.45,3647.12
  Bottom Layer w12: v1@10767.12,3554.93 v1(10767.12,3557.64) 10765.65,3557.64 10733.47,3525.46 10733.47,3143.13 10771.29,3105.31 R12_A4.1@10771.29,3098.81 ; v1@10774,3561.81 10787.59,3561.81 10814.46,3588.69 10844.04,3588.69 10857.62,3602.26 10883.94,3602.26 C5_A4.1@10930.26,3648.58
  Bottom Layer w20: D8_A4.1@10453.14,4070.96 10469.7,4087.52 D8_A4.1@10469.7,4103.46
  other v1: 10758.93,2961.19 10788.46,2961.19 10758.93,2994.38 10788.46,2994.38 10758.93,3027.56 10788.46,3027.56
CELL_BB_A1: C99_A1.1 J2_A1.15 R79_A1.2 | length 361.3
  Top Layer w8: R79_A1.2@3366.1,3432.46 3366.1,3479.88 v1(3447.19,3560.97) 3447.19,3564.76 3437.05,3574.9 3437.05,3637.34 J2_A1.15@3427.27,3647.12
  Bottom Layer w8: v1(3447.19,3560.97) 3447.19,3607.02 C99_A1.1@3488.75,3648.58
CELL_BB_A2: C99_A2.1 J2_A2.15 R79_A2.2 | length 361.3
  Top Layer w8: R79_A2.2@5661.12,3432.46 5661.12,3479.88 v1(5742.21,3560.97) 5742.21,3564.76 5732.07,3574.9 5732.07,3637.34 J2_A2.15@5722.29,3647.12
  Bottom Layer w8: v1(5742.21,3560.97) 5742.21,3607.02 C99_A2.1@5783.76,3648.58
CELL_BB_A3: C99_A3.1 J2_A3.15 R79_A3.2 | length 361.3
  Top Layer w8: R79_A3.2@7997.72,3435.67 7997.72,3483.08 v1(8078.8,3564.17) 8078.8,3567.96 8068.66,3578.1 8068.66,3640.55 J2_A3.15@8058.88,3650.33
  Bottom Layer w8: v1(8078.8,3564.17) 8078.8,3610.23 C99_A3.1@8120.36,3651.79
CELL_BB_A4: C99_A4.1 J2_A4.15 R79_A4.2 | length 361.3
  Top Layer w8: R79_A4.2@10317.95,3432.46 10317.95,3479.88 v1(10399.03,3560.97) 10399.03,3564.76 10388.89,3574.9 10388.89,3637.34 J2_A4.15@10379.11,3647.12
  Bottom Layer w8: v1(10399.03,3560.97) 10399.03,3607.02 C99_A4.1@10440.59,3648.58
COMHN_A1: C150_A1.1 R193_A1.1 U1_A1.45 | length 605
  Top Layer w8: U1_A1.45@3298.05,1082.55 3298.05,1032.66 3372.55,958.16 3372.55,879.7 3347.63,854.78 C150_A1.1@3347.63,853.8 3347.63,852.81 3378.2,822.24 3378.2,766.2 3356.58,744.58 3332.07,744.58 3310.44,722.96 3310.44,632.71 3351.38,591.78 R193_A1.1@3352.36,591.78
COMHN_A2: C150_A2.1 R193_A2.1 U1_A2.45 | length 605
  Top Layer w8: U1_A2.45@5593.07,1082.55 5593.07,1032.66 5667.57,958.16 5667.57,879.7 5642.65,854.78 C150_A2.1@5642.65,853.8 5642.65,852.81 5673.22,822.24 5673.22,766.2 5651.6,744.58 5627.08,744.58 5605.46,722.96 5605.46,632.71 5646.39,591.78 R193_A2.1@5647.38,591.78
COMHN_A3: C150_A3.1 R193_A3.1 U1_A3.45 | length 605
  Top Layer w8: U1_A3.45@7929.66,1085.75 7929.66,1035.87 8004.16,961.37 8004.16,882.91 7979.24,857.99 C150_A3.1@7979.24,857.01 7979.24,856.02 8009.82,825.45 8009.82,769.41 7988.19,747.79 7963.68,747.79 7942.06,726.16 7942.06,635.92 7982.99,594.99 R193_A3.1@7983.97,594.99
COMHN_A4: C150_A4.1 R193_A4.1 U1_A4.45 | length 447.9
  Top Layer w8: U1_A4.45@10249.89,1082.55 10249.89,1032.66 10324.39,958.16 10324.39,879.7 10299.47,854.78 C150_A4.1@10299.47,853.8 10299.47,852.81 10330.05,822.24 10330.05,716.86 10321.85,708.66 R193_A4.1@10305.12,708.66
COMHP_A1: C151_A1.1 R180_A1.1 U1_A1.46 | length 506.6
  Top Layer w8: U1_A1.46@3317.74,1082.55 3317.74,1036.2 3390.81,963.13 3390.81,868.78 3414.33,868.78 C151_A1.1@3429.04,854.08 ; R180_A1.1@3353.42,668.03 3354.41,668.03 3398.46,712.08 3398.46,822.24 3429.04,852.81 C151_A1.1@3429.04,854.08 ; C151_A1.1@3429.04,853.8 C151_A1.1@3429.04,854.08
COMHP_A2: C151_A2.1 R180_A2.1 U1_A2.46 | length 506.6
  Top Layer w8: U1_A2.46@5612.75,1082.55 5612.75,1036.2 5685.83,963.13 5685.83,868.78 5709.35,868.78 C151_A2.1@5724.05,854.08 ; R180_A2.1@5648.44,668.03 5649.42,668.03 5693.48,712.08 5693.48,822.24 5724.05,852.81 C151_A2.1@5724.05,854.08 ; C151_A2.1@5724.05,853.8 C151_A2.1@5724.05,854.08
COMHP_A3: C151_A3.1 R180_A3.1 U1_A3.46 | length 506.6
  Top Layer w8: U1_A3.46@7949.35,1085.75 7949.35,1039.41 8022.42,966.34 8022.42,871.99 8045.95,871.99 C151_A3.1@8060.65,857.29 ; R180_A3.1@7985.03,671.24 7986.02,671.24 8030.07,715.29 8030.07,825.45 8060.65,856.02 C151_A3.1@8060.65,857.29 ; C151_A3.1@8060.65,857.01 C151_A3.1@8060.65,857.29
COMHP_A4: C151_A4.1 R180_A4.1 U1_A4.46 | length 481.4
  Top Layer w8: U1_A4.46@10269.58,1082.55 10269.58,1036.2 10342.65,963.13 10342.65,868.78 10366.18,868.78 C151_A4.1@10380.88,854.08 ; C151_A4.1@10380.88,853.8 C151_A4.1@10380.88,854.08 ; R180_A4.1@10384.26,701.5 10383.54,700.79 10363,700.79 10350.3,713.48 10350.3,822.24 10380.88,852.81 C151_A4.1@10380.88,854.08
COMLN_A1: C149_A1.1 R192_A1.2 U1_A1.44 | length 530.1
  Top Layer w8: R192_A1.2@3209.53,591.38 3224.23,606.08 3233.8,606.08 3241.6,613.88 3241.6,695.56 3241.29,695.87 3241.29,810.2 3283.85,852.75 C149_A1.1@3283.85,853.74 3280.89,856.69 3280.94,856.74 3280.94,1016.89 3278.37,1019.47 U1_A1.44@3278.37,1082.55
COMLN_A2: C149_A2.1 R192_A2.2 U1_A2.44 | length 530.1
  Top Layer w8: R192_A2.2@5504.54,591.38 5519.24,606.08 5528.81,606.08 5536.61,613.88 5536.61,695.56 5536.31,695.87 5536.31,810.2 5578.86,852.75 C149_A2.1@5578.86,853.74 5575.91,856.69 5575.96,856.74 5575.96,1016.89 5573.38,1019.47 U1_A2.44@5573.38,1082.55
COMLN_A3: C149_A3.1 R192_A3.2 U1_A3.44 | length 530.1
  Top Layer w8: R192_A3.2@7841.14,594.59 7855.84,609.29 7865.41,609.29 7873.21,617.09 7873.21,698.77 7872.91,699.08 7872.91,813.41 7915.46,855.96 C149_A3.1@7915.46,856.94 7912.51,859.9 7912.55,859.94 7912.55,1020.1 7909.98,1022.67 U1_A3.44@7909.98,1085.75
COMLN_A4: C149_A4.1 R192_A4.2 U1_A4.44 | length 530.1
  Top Layer w8: R192_A4.2@10161.37,591.38 10176.07,606.08 10185.64,606.08 10193.44,613.88 10193.44,695.56 10193.14,695.87 10193.14,810.2 10235.69,852.75 C149_A4.1@10235.69,853.74 10232.74,856.69 10232.78,856.74 10232.78,1016.89 10230.21,1019.47 U1_A4.44@10230.21,1082.55
COMLP_A1: C152_A1.1 R179_A1.2 U1_A1.43 | length 462.4
  Top Layer w8: R179_A1.2@3210.04,671.95 3210.72,671.95 3225.42,686.65 3225.42,822.37 3194.84,852.94 C152_A1.1@3194.84,853.92 3194.84,854.91 3229.78,889.84 3230.86,889.84 3265.07,924.05 3265.07,1010.32 3258.68,1016.7 U1_A1.43@3258.68,1082.55
COMLP_A2: C152_A2.1 R179_A2.2 U1_A2.43 | length 462.4
  Top Layer w8: R179_A2.2@5505.05,671.95 5505.73,671.95 5520.43,686.65 5520.43,822.37 5489.86,852.94 C152_A2.1@5489.86,853.92 5489.86,854.91 5524.8,889.84 5525.87,889.84 5560.08,924.05 5560.08,1010.32 5553.7,1016.7 U1_A2.43@5553.7,1082.55
COMLP_A3: C152_A3.1 R179_A3.2 U1_A3.43 | length 462.4
  Top Layer w8: R179_A3.2@7841.65,675.15 7842.33,675.15 7857.03,689.85 7857.03,825.57 7826.46,856.15 C152_A3.1@7826.46,857.13 7826.46,858.12 7861.39,893.05 7862.47,893.05 7896.68,927.26 7896.68,1013.52 7890.29,1019.91 U1_A3.43@7890.29,1085.75
COMLP_A4: C152_A4.1 R179_A4.2 U1_A4.43 | length 462.4
  Top Layer w8: R179_A4.2@10161.88,671.95 10162.56,671.95 10177.26,686.65 10177.26,822.37 10146.69,852.94 C152_A4.1@10146.69,853.92 10146.69,854.91 10181.62,889.84 10182.7,889.84 10216.91,924.05 10216.91,1010.32 10210.52,1016.7 U1_A4.43@10210.52,1082.55
COMMH_A1_N: R187_A1.1 R189_A1.1 R193_A1.2 R194_A1.1 | length 289.4
  Top Layer w8: R193_A1.2@3415.35,591.78 3416.34,591.78 3465.69,542.43 3465.69,539.03 R189_A1.1@3480.39,524.33 3575.37,524.33 R194_A1.1@3577.37,522.34 3578.35,522.34 3625.66,569.65 3625.66,576.55 3639.66,590.55 R187_A1.1@3641.73,590.55
COMMH_A1_P: R180_A1.2 R181_A1.1 R185_A1.2 R187_A1.2 | length 287.4
  Top Layer w8: R180_A1.2@3416.41,668.03 3417.4,668.03 3461.88,712.51 3467.72,712.51 R185_A1.2@3479.47,724.26 ; R185_A1.2@3482.42,728.19 3482.57,728.35 R181_A1.1@3573.74,728.35 ; R181_A1.1@3582.68,728.35 R181_A1.1@3573.74,728.35 ; R187_A1.2@3640.36,655.23 3640.36,656.21 3587.22,709.35 3587.22,714.87 R181_A1.1@3573.74,728.35
COMMH_A2_N: R187_A2.1 R189_A2.1 R193_A2.2 R194_A2.1 | length 289.4
  Top Layer w8: R193_A2.2@5710.37,591.78 5711.35,591.78 5760.7,542.43 5760.7,539.03 R189_A2.1@5775.4,524.33 5870.39,524.33 R194_A2.1@5872.38,522.34 5873.37,522.34 5920.68,569.65 5920.68,576.55 5934.68,590.55 R187_A2.1@5936.75,590.55
COMMH_A2_P: R180_A2.2 R181_A2.1 R185_A2.2 R187_A2.2 | length 287.4
  Top Layer w8: R180_A2.2@5711.43,668.03 5712.41,668.03 5756.89,712.51 5762.74,712.51 R185_A2.2@5774.48,724.26 ; R185_A2.2@5777.44,728.19 5777.59,728.35 R181_A2.1@5868.76,728.35 ; R181_A2.1@5877.69,728.35 R181_A2.1@5868.76,728.35 ; R187_A2.2@5935.38,655.23 5935.38,656.21 5882.24,709.35 5882.24,714.87 R181_A2.1@5868.76,728.35
COMMH_A3_N: R187_A3.1 R189_A3.1 R193_A3.2 R194_A3.1 | length 289.4
  Top Layer w8: R193_A3.2@8046.97,594.99 8047.95,594.99 8097.3,545.64 8097.3,542.24 R189_A3.1@8112,527.54 8206.99,527.54 R194_A3.1@8208.98,525.55 8209.97,525.55 8257.27,572.85 8257.27,579.76 8271.27,593.76 R187_A3.1@8273.34,593.76
COMMH_A3_P: R180_A3.2 R181_A3.1 R185_A3.2 R187_A3.2 | length 287.4
  Top Layer w8: R180_A3.2@8048.03,671.24 8049.01,671.24 8093.49,715.72 8099.33,715.72 R185_A3.2@8111.08,727.46 ; R185_A3.2@8114.03,731.4 8114.19,731.55 R181_A3.1@8205.35,731.55 ; R181_A3.1@8214.29,731.55 R181_A3.1@8205.35,731.55 ; R187_A3.2@8271.97,658.44 8271.97,659.42 8218.83,712.56 8218.83,718.08 R181_A3.1@8205.35,731.55
COMMH_A4_N: R187_A4.1 R189_A4.1 R193_A4.2 R194_A4.1 | length 8332.9
  Top Layer w8: R187_A4.1@2597.47,98.43 2611.47,112.43 2611.47,119.33 2658.78,166.64 R194_A4.1@2659.77,166.64 2661.76,164.64 R189_A4.1@2756.75,164.64 2842.65,78.74 10265.75,78.74 10334.65,147.64 10334.65,617.42 10329.96,622.11 10329.66,622.11 10314.96,636.81 R193_A4.2@10314.96,637.8
COMMH_A4_P: R180_A4.2 R181_A4.1 R185_A4.2 R187_A4.2 | length 8395.9
  Top Layer w8: R187_A4.2@2596.77,33.75 2596.77,32.76 2649.91,-20.38 2649.91,-25.89 2663.39,-39.37 2754.56,-39.37 R185_A4.2@2754.71,-39.22 2843.14,49.21 10295.28,49.21 10364.17,118.11 10364.17,618.14 10368.86,622.83 10369.56,622.83 10384.26,637.53 R180_A4.2@10384.26,638.51
COMMH_N_OPT_A1: C163.1 J4_A1.2 R195_A1.2 T2.3 | length 637.5
  Top Layer w8: R195_A1.2@3774.76,522.34 3775.74,522.34 3815.59,562.19 3877.43,562.19 J4_A1.2@3883.27,568.03 3929.64,521.65 T2.3@4035.43,521.65
  Bottom Layer w8: J4_A1.2@3883.27,568.03 3929.64,521.65 C163.1@4202.76,521.65
COMMH_N_OPT_A2: C164.1 J4_A2.2 R195_A2.2 T3.3 | length 606.7
  Top Layer w8: R195_A2.2@6069.78,522.34 6070.76,522.34 6110.61,562.19 6172.45,562.19 J4_A2.2@6178.29,568.03 6219.9,568.03 6267.98,519.95 ; 6269.69,521.65 6271.26,520.08 T3.3@6311.52,520.08
  Bottom Layer w8: J4_A2.2@6178.29,568.03 6224.67,521.65 C164.1@6486.22,521.65
COMMH_N_OPT_A3: C165.1 J4_A3.2 R195_A3.2 T4.3 | length 630
  Top Layer w8: R195_A3.2@8406.37,525.55 8407.36,525.55 8447.21,565.4 8509.04,565.4 J4_A3.2@8514.89,571.24 8586.64,571.24 8636.22,521.65 T4.3@8661.42,521.65
  Bottom Layer w8: J4_A3.2@8513.78,570.87 J4_A3.2@8514.89,570.87 ; J4_A3.2@8514.89,571.24 8564.47,521.65 C165.1@8820.87,521.65 C165.1@8828.74,521.65
COMMH_N_OPT_A4: J4_A4.2 R195_A4.2 T5.6 | length 327.5
  Top Layer w8: T5.6@2165.35,147.64 2165.35,146.83 2171.2,140.99 2245.6,140.99 2265.64,120.95 J4_A4.2@2353.86,120.95 2359.7,126.79 2421.54,126.79 2461.39,166.64 R195_A4.2@2462.37,166.64
COMMH_P_OPT_A1: C153.2 J4_A1.1 R182_A1.2 T2.1 | length 628.1
  Top Layer w8: R182_A1.2@3774.76,729.57 3775.74,729.57 3819.18,686.14 3822.93,686.14 3841.04,668.03 J4_A1.1@3883.27,668.03 3934.13,718.89 3986.22,718.89 3986.6,718.5 T2.1@4025.59,718.5
  Bottom Layer w8: J4_A1.1@3883.27,668.03 3933.74,718.5 C153.2@4192.91,718.5
COMMH_P_OPT_A2: C154.2 J4_A2.1 R182_A2.2 T3.1 | length 617.8
  Top Layer w8: R182_A2.2@6069.78,729.57 6070.76,729.57 6114.19,686.14 6117.94,686.14 6136.05,668.03 J4_A2.1@6178.29,668.03 6229.14,718.89 6269.69,718.89 ; 6269.69,718.5 6309.94,718.5 T3.1@6311.52,720.08
  Bottom Layer w8: J4_A2.1@6178.29,668.03 6218.93,708.66 6476.38,708.66 C154.2@6486.22,718.5
COMMH_P_OPT_A3: C155.2 J4_A3.1 R182_A3.2 T4.1 | length 617.3
  Top Layer w8: R182_A3.2@8406.37,732.78 8407.36,732.78 8450.79,689.34 8454.54,689.34 8472.65,671.24 J4_A3.1@8514.89,671.24 8546.84,703.18 8547.67,703.18 8564.57,720.08 T4.1@8654.04,720.08
  Bottom Layer w8: J4_A3.1@8523.62,669.29 8523.62,679.97 8562.16,718.5 C155.2@8820.87,718.5
COMMH_P_OPT_A4: J4_A4.1 R182_A4.2 T5.4 | length 354.7
  Top Layer w8: T5.4@2165.35,-59.06 2273.85,-59.06 J4_A4.1@2352.48,19.57 ; J4_A4.1@2352.36,19.68 2355.12,19.68 2415.4,-40.59 R182_A4.2@2462.37,-40.59
COMML_A1_N: R186_A1.1 R188_A1.1 R191_A1.2 R192_A1.1 | length 624.8
  Top Layer w8: R186_A1.1@2596.75,619.13 2611.45,604.43 2611.45,587.71 2652.49,546.67 R191_A1.2@2653.48,546.67 2750.57,546.67 R188_A1.1@2755.91,541.34 ; R188_A1.1@2764.06,549.35 2786.76,549.35 2857.49,620.08 3117.84,620.08 R192_A1.1@3146.53,591.38
COMML_A1_P: R178_A1.2 R179_A1.1 R184_A1.2 R186_A1.2 | length 645.1
  Top Layer w8: R186_A1.2@2596.75,682.12 2611.45,696.82 2611.45,712.33 2652.49,753.36 R178_A1.2@2653.48,753.36 2668.18,738.66 2765.27,738.66 R184_A1.2@2765.75,738.19 ; R184_A1.2@2764.06,742.26 2786.76,742.26 2879.42,649.61 3124.71,649.61 3131.36,656.26 3131.36,657.24 3146.06,671.95 R179_A1.1@3147.05,671.95
COMML_A2_N: R186_A2.1 R188_A2.1 R191_A2.2 R192_A2.1 | length 624.8
  Top Layer w8: R186_A2.1@4891.77,619.13 4906.47,604.43 4906.47,587.71 4947.51,546.67 R191_A2.2@4948.49,546.67 5045.59,546.67 R188_A2.1@5050.92,541.34 ; R188_A2.1@5059.08,549.35 5081.78,549.35 5152.51,620.08 5412.85,620.08 R192_A2.1@5441.55,591.38
COMML_A2_P: R178_A2.2 R179_A2.1 R184_A2.2 R186_A2.2 | length 645.1
  Top Layer w8: R186_A2.2@4891.77,682.12 4906.47,696.82 4906.47,712.33 4947.51,753.36 R178_A2.2@4948.49,753.36 4963.19,738.66 5060.29,738.66 R184_A2.2@5060.76,738.19 ; R184_A2.2@5059.08,742.26 5081.78,742.26 5174.43,649.61 5419.72,649.61 5426.38,656.26 5426.38,657.24 5441.08,671.95 R179_A2.1@5442.06,671.95
COMML_A3_N: R186_A3.1 R188_A3.1 R191_A3.2 R192_A3.1 | length 624.8
  Top Layer w8: R186_A3.1@7228.37,622.34 7243.07,607.64 7243.07,590.92 7284.1,549.88 R191_A3.2@7285.09,549.88 7382.19,549.88 R188_A3.1@7387.52,544.55 ; R188_A3.1@7395.67,552.55 7418.37,552.55 7489.11,623.29 7749.45,623.29 R192_A3.1@7778.15,594.59
COMML_A3_P: R178_A3.2 R179_A3.1 R184_A3.2 R186_A3.2 | length 645.1
  Top Layer w8: R186_A3.2@7228.37,685.33 7243.07,700.03 7243.07,715.53 7284.1,756.57 R178_A3.2@7285.09,756.57 7299.79,741.87 7396.89,741.87 R184_A3.2@7397.36,741.4 ; R184_A3.2@7395.67,745.47 7418.37,745.47 7511.03,652.81 7756.32,652.81 7762.97,659.47 7762.97,660.45 7777.67,675.15 R179_A3.1@7778.66,675.15
COMML_A4_N: R186_A4.1 R188_A4.1 R191_A4.2 R192_A4.1 | length 624.8
  Top Layer w8: R186_A4.1@9548.6,619.13 9563.3,604.43 9563.3,587.71 9604.33,546.67 R191_A4.2@9605.32,546.67 9702.42,546.67 R188_A4.1@9707.75,541.34 ; R188_A4.1@9715.9,549.35 9738.6,549.35 9809.34,620.08 10069.68,620.08 R192_A4.1@10098.38,591.38
COMML_A4_P: R178_A4.2 R179_A4.1 R184_A4.2 R186_A4.2 | length 645.1
  Top Layer w8: R186_A4.2@9548.6,682.12 9563.3,696.82 9563.3,712.33 9604.33,753.36 R178_A4.2@9605.32,753.36 9620.02,738.66 9717.12,738.66 R184_A4.2@9717.59,738.19 ; R184_A4.2@9715.9,742.26 9738.6,742.26 9831.26,649.61 10076.55,649.61 10083.2,656.26 10083.2,657.24 10097.9,671.95 R179_A4.1@10098.89,671.95
COMML_N_OPT_A1: J3_A1.2 R190_A1.1 T1.4 | length 432.1
  Top Layer w8: T1.4@2135.83,492.13 2312.99,492.13 2350.88,530.01 J3_A1.2@2350.88,600.27 ; J3_A1.2@2351.88,600.87 2406.09,546.67 R190_A1.1@2460.56,546.67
